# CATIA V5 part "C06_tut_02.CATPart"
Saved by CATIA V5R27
Part number: Part1
Bounding box of the stored display mesh (mm): x -75 to 75, y -125 to 125, z 0 to 28.128
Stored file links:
  E:\_Deepak\2017_Deepak\CATIA\Resources\Tutorial Files\Tutorials\c06_catia_v5_6r2016_tut\C06_tut_02.CATPart
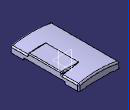
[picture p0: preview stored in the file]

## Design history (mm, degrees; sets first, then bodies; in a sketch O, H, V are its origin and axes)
Body1 (main body)
  Sketch1 on zx-plane, origin (0, 0, 0), H (-1, 0, 0), V (0, 0, 1)
    point P1 (-75, 0)
    line L1 (-75, 0) -> (75, 0)
    line L2 (75, 0) -> (75, 20)
    line L3 (-75, 20) -> (-75, 0)
    point P2 (75, 0)
    point P3 (75, 20)
    arc A1 centre (0, -321.8699) radius 350 from (75, 20) to (-75, 20) ccw
    point P6 (0, 28.1301)
    radius A1 = 350
    distance P3 P2 = 20
    distance V A1 = 350
    distance L3 L2 = 150
    coincidence: P1 H, A1 P6, P6 V
    horizontal: L1 H
    vertical: L2 V, L3 V
    symmetry: P2 P1 V
  Pad1: profile Sketch1, direction (0, 1, 0), length 125, mirrored extent
  Plane1: type Offset, RefPlane face of Pad1 from Sketch1.L1, Offset -28, reversed
  Sketch2 on Plane1, origin (0, 0, 28), H (1, 0, 0), V (0, 1, 0)
    line L1 (0, 62.5) -> (75, 62.5)
    line L2 (75, 62.5) -> (75, -62.5)
    line L3 (75, -62.5) -> (0, -62.5)
    line L4 (0, -62.5) -> (0, 62.5)
    reference projected line E1 (75, -125) -> (75, 125) from edge [face of Pad1 from Sketch1.L3 | face of Pad1 from Sketch1.A1]
    length L2 = 125
    distance H L1 = 62.5
    length L3 = 75
    horizontal: L1 H, L3 H
    vertical: L2 V, L4 V
    coincidence: L2 E1
  Pad2: profile Sketch2, direction (0, 0, 1), up to the existing solid (limit type 3)
  Draft1: Angle -3, Neutral face of Pad1 from Sketch1.L1, PullDir face of Pad1 from Sketch1.L1, SupportToDraft (end face of Pad1; face of Pad1; face of Pad1 from Sketch1.L2; start face of Pad1)
  Fillet1: radius 3, on edge [face of Pad2 from Sketch2.L3 | face of Pad2]; edge [face of Pad2 from Sketch2.L1 | face of Pad2]; edge [face of Pad1 | face of Pad2]
  Fillet2: radius 1, on edge [face of Pad1 from Sketch1.A1 | face of Pad2 from Sketch2.L1]
  Fillet3: radius 5, on edge [end face of Pad1 | face of Pad1 from Sketch1.A1]; edge [face of Pad1 from Sketch1.L2 | face of Pad1 from Sketch1.A1]; edge [start face of Pad1 | face of Pad1 from Sketch1.A1]; edge [face of Pad1 | face of Pad1 from Sketch1.A1] (x2); edge [face of Pad1 | end face of Pad1]; edge [start face of Pad1 | face of Pad1]; edge [start face of Pad1 | face of Pad1 from Sketch1.L2]; edge [face of Pad1 from Sketch1.L2 | end face of Pad1]
  Shell1: ExtOffset 0, Face face of Pad1 from Sketch1.L1, IntOffset 2
  Sketch3 on yz-plane, origin (0, 0, 0), H (0, 1, 0), V (0, 0, 1)
    line L1 (-75, 7) -> (75, 7)
    line L2 (75, 7) -> (75, -4.884)
    line L3 (75, -4.884) -> (-75, -4.884)
    line L4 (-75, -4.884) -> (-75, 7)
    point P3 (75, -4.884)
    point P4 (-75, -4.884)
    length L2 = 11.884
    distance H L1 = 7
    length L3 = 150
    horizontal: L1 H, L3 H
    vertical: L2 V, L4 V
    symmetry: P4 P3 V
  Pocket1: profile Sketch3, direction (-1, 0, 0), length 125, mirrored extent
  Sketch4 on zx-plane, origin (0, 0, 0), H (-1, 0, 0), V (0, 0, 1)
    line L1 (-50, 3) -> (50, 3)
    line L2 (50, 3) -> (50, -5.0414)
    line L3 (50, -5.0414) -> (-50, -5.0414)
    line L4 (-50, -5.0414) -> (-50, 3)
    reference projected line E1 (75, 0) -> (-75, 0) from edge [end face of Pad1 | face of Pad1 from Sketch1.L1]
    distance L2 L4 = 100
    distance V L2 = 50
    distance L1 E1 = 3
    horizontal: L1 H, L3 H
    vertical: L2 V, L4 V
  Pocket2: profile Sketch4, direction (0, -1, 0), length 133, mirrored extent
